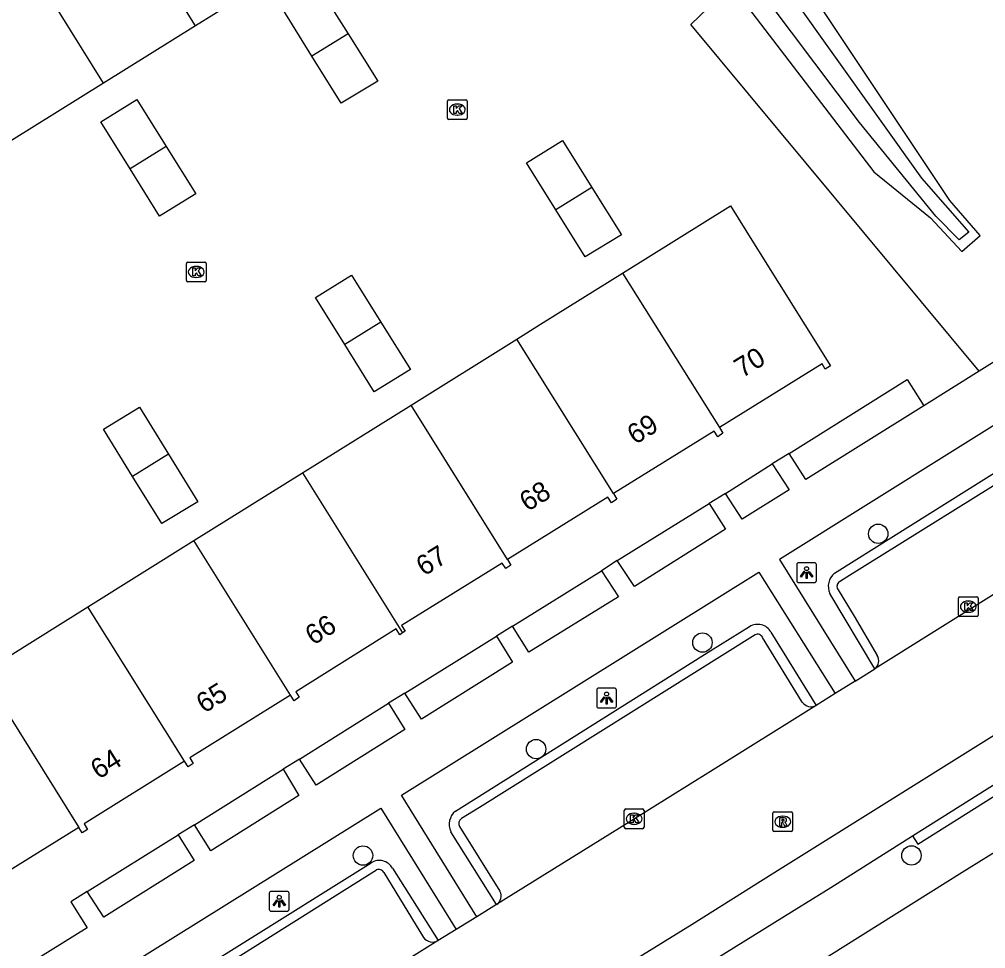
# Model space of a CAD drawing. Extents: x 159280 to 160375, y 384531 to 385872.
# Drawn here: x 159606.27 to 159655.03, y 385344.69 to 385391.6 of the extents above; entities that cross this region are included whole.
import ezdxf

# ---------------------------------------------------------------- set-up
doc = ezdxf.new("R2010")
doc.units = 0
for name, color, linetype in [('IMGEO_Boom', 7, 'Continuous'), ('IMGEO_Groenvoorziening', 7, 'Continuous'), ('IMGEO_Kolk', 7, 'Continuous'), ('IMGEO_Lichtpunt', 7, 'Continuous'), ('IMGEO_Pand', 7, 'Continuous'), ('IMGEO_Pand_nummerreeks', 7, 'Continuous'), ('IMGEO_Rijbaan_lokaal_open', 7, 'Continuous'), ('IMGEO_Rioolput', 7, 'Continuous'), ('IMGEO_Voetpad_open', 7, 'Continuous'), ('IMGEO_Waterloop', 7, 'Continuous')]:
    doc.layers.add(name, color=color, linetype=linetype)

msp = doc.modelspace()

# ---------------------------------------------------------------- linework, layer by layer
at = {"layer": 'IMGEO_Boom'}
for centre in [(159649.611, 385365.632), (159640.742, 385360.142), (159632.349, 385354.764), (159623.61, 385349.393), (159651.291, 385349.399)]:
    msp.add_circle(centre, 0.489, dxfattribs=at)
at = {"layer": 'IMGEO_Groenvoorziening'}
for points in [[(159614.908, 385428.947), (159649.394, 385383.908), (159652.246, 385381.582), (159653.836, 385379.888), (159654.761, 385380.688), (159653.222, 385382.451), (159645.751, 385393.683), (159637.569, 385404.595), (159638.588, 385405.437), (159637.617, 385406.913), (159636.237, 385406.381), (159627.182, 385417.505), (159615.488, 385431.896), (159610.601, 385428.748), (159611.342, 385427.696), (159611.824, 385427.012), (159614.908, 385428.947)], [(159654.704, 385373.839), (159640.152, 385391.343), (159641.454, 385392.593), (159636.826, 385398.323), (159635.404, 385397.306), (159624.637, 385410.931), (159623.988, 385410.51)], [(159645.11, 385369.682), (159651.078, 385373.423), (159651.917, 385372.099)], [(159641.907, 385367.672), (159644.262, 385369.162)], [(159636.446, 385364.289), (159641.073, 385367.168)], [(159631.16, 385360.972), (159635.642, 385363.77)], [(159625.716, 385357.591), (159630.342, 385360.469)], [(159620.414, 385354.258), (159624.892, 385357.078)], [(159615.108, 385350.946), (159619.584, 385353.761)], [(159609.689, 385347.581), (159614.284, 385350.439)]]:
    msp.add_lwpolyline(points, dxfattribs=at)
at = {"layer": 'IMGEO_Kolk'}
for p, q in [((159627.87, 385386.615), (159627.87, 385387.467)), ((159627.945, 385387.541), (159628.797, 385387.541)), ((159628.358, 385387.321), (159628.383, 385387.321)), ((159628.871, 385387.467), (159628.871, 385386.615)), ((159628.381, 385386.761), (159628.356, 385386.761)), ((159628.797, 385386.541), (159627.945, 385386.541)), ((159614.771, 385379.348), (159615.623, 385379.348)), ((159614.696, 385378.422), (159614.696, 385379.274)), ((159615.184, 385379.128), (159615.209, 385379.128)), ((159615.697, 385379.274), (159615.697, 385378.422)), ((159615.207, 385378.568), (159615.182, 385378.568)), ((159615.623, 385378.348), (159614.771, 385378.348)), ((159653.657, 385361.529), (159653.657, 385362.381)), ((159653.732, 385362.455), (159654.584, 385362.455)), ((159654.658, 385362.381), (159654.658, 385361.529)), ((159654.145, 385362.235), (159654.17, 385362.235)), ((159654.584, 385361.455), (159653.732, 385361.455)), ((159654.168, 385361.675), (159654.143, 385361.675)), ((159636.796, 385350.822), (159636.796, 385351.674)), ((159636.871, 385351.748), (159637.723, 385351.748)), ((159637.797, 385351.674), (159637.797, 385350.822)), ((159637.284, 385351.528), (159637.309, 385351.528)), ((159637.723, 385350.748), (159636.871, 385350.748)), ((159637.307, 385350.968), (159637.282, 385350.968))]:
    msp.add_line(p, q, dxfattribs=at)
for points in [[(159627.87, 385386.615), (159627.87, 385387.467)], [(159627.945, 385387.541), (159628.797, 385387.541)], [(159628.191, 385387.241), (159628.314, 385387.241), (159628.314, 385387.09), (159628.444, 385387.241), (159628.608, 385387.241), (159628.462, 385387.09), (159628.615, 385386.841), (159628.463, 385386.841), (159628.378, 385387.005), (159628.314, 385386.938), (159628.314, 385386.841), (159628.191, 385386.841), (159628.191, 385387.241)], [(159628.871, 385387.467), (159628.871, 385386.615)], [(159628.797, 385386.541), (159627.945, 385386.541)], [(159614.771, 385379.348), (159615.623, 385379.348)], [(159614.696, 385378.422), (159614.696, 385379.274)], [(159615.017, 385379.048), (159615.14, 385379.048), (159615.14, 385378.897), (159615.27, 385379.048), (159615.434, 385379.048), (159615.288, 385378.897), (159615.441, 385378.648), (159615.289, 385378.648), (159615.204, 385378.812), (159615.14, 385378.745), (159615.14, 385378.648), (159615.017, 385378.648), (159615.017, 385379.048)], [(159615.697, 385379.274), (159615.697, 385378.422)], [(159615.623, 385378.348), (159614.771, 385378.348)], [(159653.657, 385361.529), (159653.657, 385362.381)], [(159653.732, 385362.455), (159654.584, 385362.455)], [(159654.658, 385362.381), (159654.658, 385361.529)], [(159653.978, 385362.155), (159654.101, 385362.155), (159654.101, 385362.004), (159654.231, 385362.155), (159654.395, 385362.155), (159654.249, 385362.004), (159654.402, 385361.755), (159654.25, 385361.755), (159654.165, 385361.919), (159654.101, 385361.852), (159654.101, 385361.755), (159653.978, 385361.755), (159653.978, 385362.155)], [(159654.584, 385361.455), (159653.732, 385361.455)], [(159636.796, 385350.822), (159636.796, 385351.674)], [(159636.871, 385351.748), (159637.723, 385351.748)], [(159637.797, 385351.674), (159637.797, 385350.822)], [(159637.117, 385351.448), (159637.24, 385351.448), (159637.24, 385351.297), (159637.37, 385351.448), (159637.534, 385351.448), (159637.388, 385351.297), (159637.541, 385351.048), (159637.389, 385351.048), (159637.304, 385351.212), (159637.24, 385351.145), (159637.24, 385351.048), (159637.117, 385351.048), (159637.117, 385351.448)], [(159637.723, 385350.748), (159636.871, 385350.748)]]:
    msp.add_lwpolyline(points, dxfattribs=at)
for centre, start, end in [((159627.947, 385387.465), 91.552, 178.448), ((159627.947, 385387.465), 91.552, 178.448), ((159628.795, 385387.465), 1.552, 88.448), ((159628.795, 385387.465), 1.552, 88.448), ((159627.947, 385386.617), 181.552, 268.448), ((159627.947, 385386.617), 181.552, 268.448), ((159628.795, 385386.617), 271.552, 358.448), ((159628.795, 385386.617), 271.552, 358.448), ((159614.773, 385379.272), 91.552, 178.448), ((159614.773, 385379.272), 91.552, 178.448), ((159615.621, 385379.272), 1.552, 88.448), ((159615.621, 385379.272), 1.552, 88.448), ((159614.773, 385378.424), 181.552, 268.448), ((159614.773, 385378.424), 181.552, 268.448), ((159615.621, 385378.424), 271.552, 358.448), ((159615.621, 385378.424), 271.552, 358.448), ((159653.734, 385362.379), 91.552, 178.448), ((159653.734, 385362.379), 91.552, 178.448), ((159654.582, 385362.379), 1.552, 88.448), ((159654.582, 385362.379), 1.552, 88.448), ((159653.734, 385361.531), 181.552, 268.448), ((159653.734, 385361.531), 181.552, 268.448), ((159654.582, 385361.531), 271.552, 358.448), ((159654.582, 385361.531), 271.552, 358.448), ((159636.873, 385351.672), 91.552, 178.448), ((159636.873, 385351.672), 91.552, 178.448), ((159637.721, 385351.672), 1.552, 88.448), ((159637.721, 385351.672), 1.552, 88.448), ((159636.873, 385350.824), 181.552, 268.448), ((159636.873, 385350.824), 181.552, 268.448), ((159637.721, 385350.824), 271.552, 358.448), ((159637.721, 385350.824), 271.552, 358.448)]:
    msp.add_arc(centre, 0.0765, start, end, dxfattribs=at)
for centre, major_axis, ratio, start_param, end_param in [((159628.357, 385387.041), (-0.387, 0.002), 0.722429, 4.712389, 7.853982), ((159628.382, 385387.041), (-0.39, 0.002), 0.717154, 1.570796, 4.712389), ((159615.183, 385378.848), (-0.387, 0.002), 0.722429, 4.712389, 7.853982), ((159615.208, 385378.848), (-0.39, 0.002), 0.717154, 1.570796, 4.712389), ((159654.144, 385361.955), (-0.387, 0.002), 0.722429, 4.712389, 7.853982), ((159654.169, 385361.955), (-0.39, 0.002), 0.717154, 1.570796, 4.712389), ((159637.283, 385351.248), (-0.387, 0.002), 0.722429, 4.712389, 7.853982), ((159637.308, 385351.248), (-0.39, 0.002), 0.717154, 1.570796, 4.712389)]:
    msp.add_ellipse(centre, major_axis=major_axis, ratio=ratio, start_param=start_param, end_param=end_param, dxfattribs=at)
at = {"layer": 'IMGEO_Lichtpunt'}
for p, q in [((159645.499, 385364.075), (159645.499, 385363.268)), ((159645.499, 385364.075), (159645.499, 385363.268)), ((159646.401, 385364.17), (159645.593, 385364.17)), ((159646.401, 385364.17), (159645.593, 385364.17)), ((159646.495, 385363.268), (159646.495, 385364.075)), ((159646.495, 385363.268), (159646.495, 385364.075)), ((159645.593, 385363.174), (159646.401, 385363.174)), ((159645.593, 385363.174), (159646.401, 385363.174)), ((159635.404, 385357.748), (159635.404, 385356.941)), ((159635.404, 385357.748), (159635.404, 385356.941)), ((159636.306, 385357.843), (159635.498, 385357.843)), ((159636.306, 385357.843), (159635.498, 385357.843)), ((159636.4, 385356.941), (159636.4, 385357.748)), ((159636.4, 385356.941), (159636.4, 385357.748)), ((159635.498, 385356.847), (159636.306, 385356.847)), ((159635.498, 385356.847), (159636.306, 385356.847)), ((159618.883, 385347.489), (159618.883, 385346.682)), ((159618.883, 385347.489), (159618.883, 385346.682)), ((159619.785, 385347.584), (159618.977, 385347.584)), ((159619.785, 385347.584), (159618.977, 385347.584)), ((159619.879, 385346.682), (159619.879, 385347.489)), ((159619.879, 385346.682), (159619.879, 385347.489)), ((159618.977, 385346.588), (159619.785, 385346.588)), ((159618.977, 385346.588), (159619.785, 385346.588))]:
    msp.add_line(p, q, dxfattribs=at)
for points in [[(159645.873, 385363.739), (159645.912, 385363.711), (159645.724, 385363.449), (159645.686, 385363.476), (159645.873, 385363.739)], [(159646.085, 385363.711), (159646.123, 385363.738), (159646.31, 385363.476), (159646.271, 385363.448), (159646.085, 385363.711)], [(159645.975, 385363.691), (159646.022, 385363.691), (159646.022, 385363.369), (159645.975, 385363.369), (159645.975, 385363.691)], [(159635.778, 385357.412), (159635.817, 385357.384), (159635.629, 385357.122), (159635.591, 385357.149), (159635.778, 385357.412)], [(159635.99, 385357.384), (159636.028, 385357.411), (159636.215, 385357.149), (159636.176, 385357.121), (159635.99, 385357.384)], [(159635.88, 385357.364), (159635.927, 385357.364), (159635.927, 385357.042), (159635.88, 385357.042), (159635.88, 385357.364)], [(159619.257, 385347.153), (159619.296, 385347.125), (159619.108, 385346.863), (159619.07, 385346.89), (159619.257, 385347.153)], [(159619.469, 385347.125), (159619.507, 385347.152), (159619.694, 385346.89), (159619.655, 385346.862), (159619.469, 385347.125)], [(159619.359, 385347.105), (159619.406, 385347.105), (159619.406, 385346.783), (159619.359, 385346.783), (159619.359, 385347.105)]]:
    msp.add_lwpolyline(points, dxfattribs=at)
for centre in [(159645.998, 385363.873), (159635.903, 385357.546), (159619.382, 385347.287)]:
    msp.add_circle(centre, 0.0994, dxfattribs=at)
for centre, start, end in [((159645.593, 385364.075), 90, 180), ((159645.593, 385364.075), 90, 180), ((159646.401, 385364.075), 0, 90), ((159646.401, 385364.075), 0, 90), ((159645.593, 385363.268), 180, 270), ((159645.593, 385363.268), 180, 270), ((159646.401, 385363.268), 270, 0), ((159646.401, 385363.268), 270, 360), ((159635.498, 385357.748), 90, 180), ((159635.498, 385357.748), 90, 180), ((159636.306, 385357.748), 0, 90), ((159636.306, 385357.748), 0, 90), ((159635.498, 385356.941), 180, 270), ((159635.498, 385356.941), 180, 270), ((159636.306, 385356.941), 270, 0), ((159636.306, 385356.941), 270, 360), ((159618.977, 385347.489), 90, 180), ((159618.977, 385347.489), 90, 180), ((159619.785, 385347.489), 0, 90), ((159619.785, 385347.489), 0, 90), ((159618.977, 385346.682), 180, 270), ((159618.977, 385346.682), 180, 270), ((159619.785, 385346.682), 270, 0), ((159619.785, 385346.682), 270, 360)]:
    msp.add_arc(centre, 0.0946, start, end, dxfattribs=at)
at = {"layer": 'IMGEO_Pand'}
for points in [[(159615.151, 385391.265), (159609.657, 385400.082)], [(159610.512, 385388.375), (159605.024, 385397.183)], [(159619.789, 385394.155), (159615.151, 385391.265)], [(159621.037, 385389.736), (159619.56, 385392.111), (159621.37, 385393.238), (159622.856, 385390.867)], [(159615.151, 385391.265), (159610.512, 385388.375)], [(159622.856, 385390.867), (159624.353, 385388.479), (159622.513, 385387.361), (159621.037, 385389.736)], [(159622.856, 385390.867), (159621.037, 385389.736)], [(159610.512, 385388.375), (159605.874, 385385.485)], [(159611.857, 385384.047), (159610.38, 385386.422), (159612.19, 385387.549), (159613.676, 385385.178)], [(159633.344, 385381.983), (159631.867, 385384.358), (159633.677, 385385.485), (159635.163, 385383.114)], [(159613.676, 385385.178), (159615.173, 385382.79), (159613.333, 385381.672), (159611.857, 385384.047)], [(159613.676, 385385.178), (159611.857, 385384.047)], [(159635.163, 385383.114), (159636.66, 385380.726), (159634.82, 385379.608), (159633.344, 385381.983)], [(159635.163, 385383.114), (159633.344, 385381.983)], [(159636.711, 385378.791), (159642.161, 385382.189), (159643.326, 385380.32), (159647.2, 385374.107), (159646.929, 385373.945), (159646.785, 385374.208), (159641.594, 385371.001)], [(159622.693, 385375.179), (159621.216, 385377.554), (159623.026, 385378.681), (159624.512, 385376.31)], [(159631.377, 385375.464), (159632.574, 385376.211), (159636.711, 385378.791)], [(159636.711, 385378.791), (159641.594, 385371.001)], [(159624.512, 385376.31), (159626.009, 385373.922), (159624.169, 385372.804), (159622.693, 385375.179)], [(159624.512, 385376.31), (159622.693, 385375.179)], [(159626.037, 385372.131), (159631.377, 385375.464)], [(159636.246, 385367.663), (159631.377, 385375.464)], [(159620.562, 385368.714), (159626.037, 385372.131)], [(159630.905, 385364.331), (159626.037, 385372.131)], [(159611.984, 385368.53), (159610.513, 385370.915), (159612.326, 385372.016), (159613.795, 385369.647)], [(159641.594, 385371.001), (159641.765, 385370.711), (159641.511, 385370.535), (159641.33, 385370.816), (159636.246, 385367.663)], [(159613.795, 385369.647), (159615.281, 385367.252), (159613.454, 385366.145), (159611.984, 385368.53)], [(159613.795, 385369.647), (159611.984, 385368.53)], [(159615.082, 385365.293), (159620.562, 385368.714)], [(159620.562, 385368.714), (159625.607, 385360.631)], [(159636.246, 385367.663), (159636.415, 385367.385), (159636.159, 385367.202), (159635.966, 385367.482), (159630.905, 385364.331)], [(159609.728, 385361.952), (159615.082, 385365.293)], [(159619.95, 385357.493), (159615.082, 385365.293)], [(159630.905, 385364.331), (159631.078, 385364.052), (159630.817, 385363.876), (159630.638, 385364.156), (159625.555, 385361.001), (159625.74, 385360.722), (159625.607, 385360.631)], [(159604.39, 385358.62), (159609.728, 385361.952)], [(159614.598, 385354.15), (159609.728, 385361.952)], [(159625.607, 385360.631), (159625.471, 385360.537), (159625.285, 385360.831), (159620.216, 385357.658), (159620.393, 385357.386), (159620.131, 385357.209), (159619.95, 385357.493)], [(159609.263, 385350.813), (159604.11, 385347.605), (159604.246, 385347.31), (159604.01, 385347.149), (159603.277, 385348.324), (159599.755, 385353.97), (159598.966, 385355.235), (159604.39, 385358.62)], [(159604.39, 385358.62), (159609.263, 385350.813)], [(159619.95, 385357.493), (159614.868, 385354.325), (159615.046, 385354.044), (159614.784, 385353.872), (159614.598, 385354.15)], [(159614.598, 385354.15), (159609.538, 385350.989), (159609.712, 385350.709), (159609.44, 385350.535), (159609.263, 385350.813)]]:
    msp.add_lwpolyline(points, dxfattribs=at)
at = {"layer": 'IMGEO_Rijbaan_lokaal_open'}
for points in [[(159614.419, 385330.007), (159640.215, 385345.938), (159644.265, 385348.476), (159693.538, 385379.269), (159694.578, 385379.919), (159695.635, 385378.201)], [(159661.215, 385366.183), (159649.438, 385358.819)], [(159648.454, 385358.203), (159649.438, 385358.819)], [(159648.454, 385358.203), (159647.441, 385357.57)], [(159647.441, 385357.57), (159646.475, 385356.966)], [(159646.475, 385356.966), (159641.141, 385353.643), (159637.039, 385351.087), (159630.352, 385346.921)], [(159630.352, 385346.921), (159629.355, 385346.306)], [(159629.355, 385346.306), (159628.319, 385345.666)], [(159628.319, 385345.666), (159627.402, 385345.101)], [(159627.402, 385345.101), (159618.688, 385339.659), (159611.352, 385335.08)]]:
    msp.add_lwpolyline(points, dxfattribs=at)
at = {"layer": 'IMGEO_Rioolput'}
for p, q in [((159644.368, 385351.601), (159645.22, 385351.601)), ((159644.293, 385350.675), (159644.293, 385351.527)), ((159644.781, 385351.381), (159644.806, 385351.381)), ((159645.294, 385351.527), (159645.294, 385350.675)), ((159645.22, 385350.601), (159644.368, 385350.601)), ((159644.804, 385350.821), (159644.779, 385350.821))]:
    msp.add_line(p, q, dxfattribs=at)
for points in [[(159644.368, 385351.601), (159645.22, 385351.601)], [(159644.293, 385350.675), (159644.293, 385351.527)], [(159644.882, 385351.299), (159644.63, 385351.301), (159644.63, 385350.901)], [(159644.63, 385350.901), (159644.754, 385350.901), (159644.754, 385351.063), (159644.765, 385351.063)], [(159644.808, 385351.22), (159644.754, 385351.22), (159644.754, 385351.139)], [(159644.754, 385351.139), (159644.806, 385351.139)], [(159645.294, 385351.527), (159645.294, 385350.675)], [(159645.22, 385350.601), (159644.368, 385350.601)], [(159644.812, 385351.034), (159644.883, 385350.901), (159645.023, 385350.901), (159644.958, 385351.027)]]:
    msp.add_lwpolyline(points, dxfattribs=at)
for centre, radius, start, end in [((159644.37, 385351.525), 0.0765, 91.552, 178.448), ((159644.37, 385351.525), 0.0765, 91.552, 178.448), ((159645.218, 385351.525), 0.0765, 1.552, 88.448), ((159645.218, 385351.525), 0.0765, 1.552, 88.448), ((159644.764, 385351.01), 0.0533, 26.0293, 88.6989), ((159644.79, 385351.328), 0.19, 274.7715, 282.9687), ((159644.814, 385351.124), 0.0964, 77.0061, 93.1865), ((159644.828, 385351.181), 0.0378, 276.6634, 79.6772), ((159644.881, 385351.189), 0.109, 350.3612, 89.416), ((159644.879, 385351.189), 0.112, 277.5842, 350.9817), ((159644.863, 385350.974), 0.108, 29.5134, 73.7905), ((159644.37, 385350.677), 0.0765, 181.552, 268.448), ((159644.37, 385350.677), 0.0765, 181.552, 268.448), ((159645.218, 385350.677), 0.0765, 271.552, 358.448), ((159645.218, 385350.677), 0.0765, 271.552, 358.448)]:
    msp.add_arc(centre, radius, start, end, dxfattribs=at)
for centre, major_axis, ratio, start_param, end_param in [((159644.78, 385351.101), (-0.387, 0.002), 0.722429, 4.712389, 7.853982), ((159644.805, 385351.101), (-0.39, 0.002), 0.717154, 1.570796, 4.712389)]:
    msp.add_ellipse(centre, major_axis=major_axis, ratio=ratio, start_param=start_param, end_param=end_param, dxfattribs=at)
at = {"layer": 'IMGEO_Voetpad_open'}
for points in [[(159660.962, 385376.671), (159657.025, 385374.216), (159656.547, 385374.991), (159654.704, 385373.839)], [(159663.898, 385367.815), (159660.102, 385374.002), (159657.973, 385372.677), (159644.632, 385364.339), (159648.454, 385358.203)], [(159654.704, 385373.839), (159651.917, 385372.099)], [(159651.917, 385372.099), (159645.953, 385368.374), (159645.11, 385369.682)], [(159647.404, 385363.65), (159657.924, 385370.237)], [(159645.11, 385369.682), (159644.262, 385369.162)], [(159658.105, 385369.718), (159648.031, 385363.451), (159647.65, 385363.208)], [(159644.262, 385369.162), (159645.117, 385367.852), (159642.753, 385366.363), (159641.907, 385367.672)], [(159641.907, 385367.672), (159641.073, 385367.168)], [(159641.073, 385367.168), (159641.905, 385365.865), (159637.306, 385362.971), (159636.446, 385364.289)], [(159636.446, 385364.289), (159635.642, 385363.77)], [(159635.642, 385363.77), (159636.513, 385362.448), (159631.988, 385359.662), (159631.16, 385360.972)], [(159629.355, 385346.306), (159625.552, 385352.435), (159643.591, 385363.703), (159647.441, 385357.57)], [(159647.588, 385362.812), (159648.404, 385361.476), (159649.565, 385359.496)], [(159649.438, 385358.819), (159647.172, 385362.618)], [(159628.272, 385351.631), (159641.172, 385359.745), (159643.123, 385360.946)], [(159631.16, 385360.972), (159630.342, 385360.469)], [(159630.342, 385360.469), (159631.157, 385359.15), (159626.565, 385356.272), (159625.716, 385357.591)], [(159643.401, 385360.536), (159629.484, 385351.817), (159628.578, 385351.256)], [(159645.78, 385357.14), (159643.779, 385360.401)], [(159644.2, 385360.668), (159646.475, 385356.966)], [(159625.716, 385357.591), (159624.892, 385357.078)], [(159624.892, 385357.078), (159625.727, 385355.752), (159621.251, 385352.954), (159620.414, 385354.258)], [(159651.347, 385350.386), (159659.021, 385355.215)], [(159651.347, 385350.386), (159651.613, 385349.963), (159659.287, 385354.792), (159659.021, 385355.215)], [(159620.414, 385354.258), (159619.584, 385353.761)], [(159619.584, 385353.761), (159620.38, 385352.427), (159615.938, 385349.636), (159615.108, 385350.946)], [(159603.631, 385338.78), (159624.51, 385351.792), (159628.319, 385345.666)], [(159615.108, 385350.946), (159614.284, 385350.439)], [(159630.352, 385346.921), (159628.039, 385350.599)], [(159628.488, 385350.853), (159630.524, 385347.594)], [(159614.284, 385350.439), (159615.099, 385349.139), (159610.524, 385346.283), (159609.689, 385347.581)], [(159633.896, 385339.491), (159641.334, 385344.123), (159645.375, 385346.64), (159647.218, 385347.788), (159651.347, 385350.386)], [(159656.241, 385350.023), (159653.846, 385348.536), (159590.968, 385309.084)], [(159609.152, 385339.74), (159615.941, 385343.971), (159617.237, 385344.788), (159624.021, 385349.029)], [(159609.442, 385339.325), (159609.823, 385339.569), (159624.284, 385348.67)], [(159625.098, 385348.751), (159625.499, 385348.113), (159627.402, 385345.101)], [(159624.662, 385348.536), (159626.669, 385345.257)], [(159609.689, 385347.581), (159608.873, 385347.054), (159609.696, 385345.751), (159603.097, 385341.65)]]:
    msp.add_lwpolyline(points, dxfattribs=at)
for centre, radius, start, end in [((159647.965, 385362.982), 0.873, 130.0199, 204.6404), ((159647.808, 385362.98), 0.277, 124.6969, 217.5065), ((159643.53, 385360.299), 0.764, 28.849, 122.204), ((159643.523, 385360.281), 0.282, 25.0771, 115.6152), ((159649.131, 385359.227), 0.51, 306.9219, 31.8285), ((159646.222, 385357.429), 0.528, 213.2334, 298.6553), ((159628.83, 385350.963), 0.871, 129.8805, 204.6742), ((159628.739, 385351.009), 0.295, 122.9816, 211.8404), ((159624.429, 385348.383), 0.764, 28.8026, 122.2504), ((159624.406, 385348.414), 0.283, 25.4077, 115.5538), ((159630.079, 385347.349), 0.508, 302.4978, 28.8295), ((159627.124, 385345.594), 0.566, 216.5659, 299.4048)]:
    msp.add_arc(centre, radius, start, end, dxfattribs=at)
at = {"layer": 'IMGEO_Waterloop'}
msp.add_lwpolyline([(159614.743, 385429.435), (159612.183, 385427.917), (159611.797, 385428.71), (159614.426, 385430.251), (159615.083, 385430.568), (159615.491, 385430.364), (159618.187, 385426.716), (159626.072, 385416.724), (159635.272, 385405.576), (159636.609, 385405.802), (159637.198, 385405.1), (159636.926, 385403.65), (159645.219, 385392.819), (159651.79, 385383.574), (159654.192, 385380.855), (159653.693, 385380.47), (159652.515, 385381.671), (159648.663, 385386.384), (159638.421, 385400.024), (159622.878, 385419.556), (159615.808, 385428.71), (159615.4, 385429.186), (159614.743, 385429.435)], dxfattribs=at)

# ---------------------------------------------------------------- texts
at = {"layer": 'IMGEO_Pand_nummerreeks'}
for s, rotation, p in [('70', 31.7075, (159642.745, 385373.475)), ('69', 31.8049, (159637.342, 385370.108)), ('68', 31.908, (159631.913, 385366.726)), ('67', 31.8278, (159626.691, 385363.472)), ('66', 32.0455, (159621.097, 385359.979)), ('65', 31.9367, (159615.597, 385356.547)), ('64', 31.994, (159610.266, 385353.212))]:
    msp.add_text(s, height=1, rotation=rotation, dxfattribs=at).set_placement(p)

doc.saveas('drawing.dxf')
